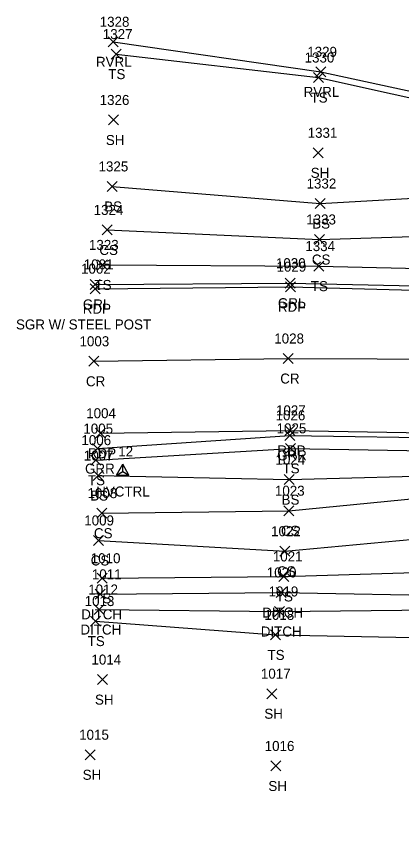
# Model space of a CAD drawing. Extents: x 1514253 to 1516033, y 782541 to 785002.
# Drawn here: x 1515182.9 to 1515259.8, y 782601.1 to 782767.3 of the extents above; entities that cross this region are included whole.
import ezdxf

# ---------------------------------------------------------------- set-up
doc = ezdxf.new("R2010")
doc.units = 0
for name, color, linetype in [('C_A', 7, 'Continuous'), ('C_I', 7, 'Continuous'), ('CPSM', 7, 'Continuous'), ('D_A', 7, 'Continuous'), ('D_I', 7, 'Continuous'), ('D_TIC', 7, 'Continuous'), ('DD', 7, 'Continuous'), ('L_A', 7, 'Continuous'), ('L_I', 7, 'Continuous'), ('L_TIC', 7, 'Continuous'), ('LAWE', 7, 'Continuous'), ('LELB', 7, 'Continuous'), ('P_A', 7, 'Continuous'), ('P_I', 7, 'Continuous'), ('P_TIC', 7, 'Continuous'), ('PET', 7, 'Continuous'), ('PRC', 7, 'Continuous'), ('R_A', 7, 'Continuous'), ('R_C', 7, 'Continuous'), ('R_I', 7, 'Continuous'), ('R_TIC', 7, 'Continuous'), ('RGR', 7, 'Continuous')]:
    doc.layers.add(name, color=color, linetype=linetype)

msp = doc.modelspace()

# ---------------------------------------------------------------- linework, layer by layer
at = {"layer": 'CPSM'}
for p, q in [((1515202.84, 782675.7), (1515204.09, 782677.87)), ((1515205.34, 782675.7), (1515204.09, 782677.87)), ((1515204.09, 782676.42), (1515204.09, 782677.87)), ((1515202.84, 782675.7), (1515204.09, 782676.42)), ((1515204.09, 782676.42), (1515204.09, 782676.42)), ((1515204.09, 782676.42), (1515205.34, 782675.7)), ((1515202.84, 782675.7), (1515205.34, 782675.7))]:
    msp.add_line(p, q, dxfattribs=at)
at = {"layer": 'D_TIC'}
for points in [[(1515198.55, 782650.88), (1515200.55, 782652.88)], [(1515200.55, 782650.88), (1515198.55, 782652.88)], [(1515234.76, 782651.24), (1515236.76, 782653.24)], [(1515236.76, 782651.24), (1515234.76, 782653.24)], [(1515198.39, 782647.84), (1515200.39, 782649.84)], [(1515200.39, 782647.84), (1515198.39, 782649.84)], [(1515234.48, 782647.45), (1515236.48, 782649.45)], [(1515236.48, 782647.45), (1515234.48, 782649.45)]]:
    msp.add_lwpolyline(points, dxfattribs=at)
at = {"layer": 'DD'}
for points in [[(1515199.55, 782651.88), (1515235.76, 782652.24), (1515272.28, 782651.56), (1515284.51, 782654.56), (1515294.12, 782653.93), (1515301.84, 782655.71), (1515302.59, 782655.7)], [(1515199.39, 782648.84), (1515235.48, 782648.45), (1515272.16, 782648.84), (1515285.61, 782648.49), (1515294.46, 782648.38), (1515312.17, 782640.18), (1515323.37, 782638.78), (1515329.31, 782640.31), (1515333.45, 782637.85), (1515333.04, 782633.95), (1515334.72, 782622.81), (1515328.39, 782601.12)]]:
    msp.add_lwpolyline(points, dxfattribs=at)
at = {"layer": 'L_TIC'}
for points in [[(1515201.17, 782761.27), (1515203.17, 782763.27)], [(1515203.17, 782761.27), (1515201.17, 782763.27)], [(1515201.79, 782758.81), (1515203.79, 782760.81)], [(1515203.79, 782758.81), (1515201.79, 782760.81)], [(1515242.26, 782754.13), (1515244.26, 782756.13)], [(1515244.26, 782754.13), (1515242.26, 782756.13)], [(1515242.71, 782755.27), (1515244.71, 782757.27)], [(1515244.71, 782755.27), (1515242.71, 782757.27)], [(1515201.22, 782745.65), (1515203.22, 782747.65)], [(1515203.22, 782745.65), (1515201.22, 782747.65)], [(1515242.22, 782739.09), (1515244.22, 782741.09)], [(1515244.22, 782739.09), (1515242.22, 782741.09)], [(1515200.95, 782732.37), (1515202.95, 782734.37)], [(1515202.95, 782732.37), (1515200.95, 782734.37)], [(1515242.57, 782728.95), (1515244.57, 782730.95)], [(1515244.57, 782728.95), (1515242.57, 782730.95)], [(1515199.97, 782723.68), (1515201.97, 782725.68)], [(1515201.97, 782723.68), (1515199.97, 782725.68)], [(1515242.49, 782721.77), (1515244.49, 782723.77)], [(1515244.49, 782721.77), (1515242.49, 782723.77)], [(1515199.03, 782716.69), (1515201.03, 782718.69)], [(1515201.03, 782716.69), (1515199.03, 782718.69)], [(1515242.31, 782716.45), (1515244.31, 782718.45)], [(1515244.31, 782716.45), (1515242.31, 782718.45)], [(1515236.65, 782680.04), (1515238.65, 782682.04)], [(1515238.65, 782680.04), (1515236.65, 782682.04)], [(1515197.72, 782677.68), (1515199.72, 782679.68)], [(1515199.72, 782677.68), (1515197.72, 782679.68)], [(1515198.15, 782674.61), (1515200.15, 782676.61)], [(1515200.15, 782674.61), (1515198.15, 782676.61)], [(1515236.42, 782673.79), (1515238.42, 782675.79)], [(1515238.42, 782673.79), (1515236.42, 782675.79)], [(1515236.31, 782667.58), (1515238.31, 782669.58)], [(1515238.31, 782667.58), (1515236.31, 782669.58)], [(1515198.89, 782667.09), (1515200.89, 782669.09)], [(1515200.89, 782667.09), (1515198.89, 782669.09)], [(1515198.25, 782661.64), (1515200.25, 782663.64)], [(1515200.25, 782661.64), (1515198.25, 782663.64)], [(1515235.54, 782659.48), (1515237.54, 782661.48)], [(1515237.54, 782659.48), (1515235.54, 782661.48)], [(1515198.98, 782654.09), (1515200.98, 782656.09)], [(1515200.98, 782654.09), (1515198.98, 782656.09)], [(1515235.32, 782654.45), (1515237.32, 782656.45)], [(1515237.32, 782654.45), (1515235.32, 782656.45)], [(1515197.67, 782645.53), (1515199.67, 782647.53)], [(1515199.67, 782645.53), (1515197.67, 782647.53)], [(1515233.65, 782642.77), (1515235.65, 782644.77)], [(1515235.65, 782642.77), (1515233.65, 782644.77)], [(1515199.04, 782633.84), (1515201.04, 782635.84)], [(1515201.04, 782633.84), (1515199.04, 782635.84)], [(1515232.94, 782631.02), (1515234.94, 782633.02)], [(1515234.94, 782631.02), (1515232.94, 782633.02)], [(1515196.58, 782618.82), (1515198.58, 782620.82)], [(1515198.58, 782618.82), (1515196.58, 782620.82)], [(1515233.75, 782616.58), (1515235.75, 782618.58)], [(1515235.75, 782616.58), (1515233.75, 782618.58)]]:
    msp.add_lwpolyline(points, dxfattribs=at)
at = {"layer": 'LAWE'}
msp.add_lwpolyline([(1515202.17, 782762.27), (1515243.71, 782756.27), (1515286.28, 782747.11), (1515297.44, 782750.04), (1515300.76, 782752.52), (1515315.46, 782751.02), (1515328.64, 782746.75), (1515343.2, 782744.52), (1515396.17, 782730.21), (1515410.48, 782726.67), (1515425.65, 782730.86), (1515462.57, 782730.18)], dxfattribs=at)
at = {"layer": 'LELB'}
for points in [[(1515202.79, 782759.81), (1515243.26, 782755.13), (1515286.87, 782745.48), (1515294.36, 782746.28), (1515301.46, 782734.49)], [(1515201.95, 782733.37), (1515243.57, 782729.95), (1515286.67, 782732.44), (1515301.66, 782731.52), (1515315.52, 782732.45), (1515331.94, 782733.39), (1515354.73, 782729.4), (1515394.7, 782722.81), (1515412.77, 782722.27)], [(1515200.97, 782724.68), (1515243.49, 782722.77), (1515286.83, 782724.14), (1515305.14, 782723.88), (1515320.01, 782723.69), (1515332.82, 782725.68), (1515355.56, 782722.1), (1515394.29, 782712.68), (1515425.22, 782714.96), (1515459.54, 782709.6)], [(1515200.03, 782717.69), (1515243.31, 782717.45), (1515286.69, 782716.43), (1515307.76, 782717.31)], [(1515198.72, 782678.68), (1515237.65, 782681.04), (1515272.58, 782680.41), (1515290.32, 782679.16), (1515303.85, 782678.5), (1515308.9, 782677.48), (1515327.05, 782677.39), (1515347.39, 782677.23), (1515355.31, 782675.99), (1515384.86, 782670.27), (1515402.64, 782668.14), (1515426.9, 782664.76), (1515431.08, 782662.88), (1515448.44, 782660.3)], [(1515199.15, 782675.61), (1515237.42, 782674.79), (1515272.57, 782675.73), (1515289.46, 782673.87), (1515300.03, 782673.18), (1515309.4, 782672.94), (1515327.02, 782671.99), (1515352.18, 782674.37), (1515355.48, 782668.37), (1515355.53, 782661.9), (1515362.2, 782656.24), (1515384.65, 782653.27), (1515398.96, 782656.38), (1515406.88, 782653.85), (1515416.3, 782653.12), (1515424.34, 782655.88), (1515430.38, 782659.61), (1515449.3, 782656.53)], [(1515199.98, 782655.09), (1515236.32, 782655.45), (1515273.42, 782656.6), (1515286.93, 782662.61), (1515299.54, 782665), (1515304.67, 782664.1), (1515305.27, 782661.39), (1515319.28, 782664.02), (1515324.87, 782660.75), (1515330.53, 782661.03), (1515335.53, 782663.34), (1515351.63, 782666.23), (1515352.18, 782674.37)], [(1515199.89, 782668.09), (1515237.31, 782668.58), (1515273.4, 782672.06), (1515287.73, 782668.03), (1515299.26, 782668.76), (1515308.35, 782666.42), (1515328.22, 782666.06), (1515330.53, 782661.03), (1515333.75, 782659.05), (1515343.88, 782659.19), (1515351.41, 782658.19), (1515355.48, 782668.37), (1515366.85, 782667.84), (1515384, 782666.14), (1515400.68, 782664.25), (1515424.65, 782661.72), (1515431.01, 782661.43), (1515448.86, 782658.44)], [(1515199.25, 782662.64), (1515236.54, 782660.48), (1515273.8, 782663.96), (1515286.93, 782662.61)], [(1515198.67, 782646.53), (1515234.65, 782643.77), (1515272.44, 782643.04), (1515272.72, 782635.52), (1515270.64, 782626.33), (1515264.31, 782620.96)]]:
    msp.add_lwpolyline(points, dxfattribs=at)
at = {"layer": 'P_TIC'}
for points in [[(1515236.64, 782712.34), (1515238.64, 782714.34)], [(1515238.64, 782712.34), (1515236.64, 782714.34)], [(1515197.6, 782711.94), (1515199.6, 782713.94)], [(1515199.6, 782711.94), (1515197.6, 782713.94)], [(1515197.29, 782697.44), (1515199.29, 782699.44)], [(1515199.29, 782697.44), (1515197.29, 782699.44)], [(1515236.18, 782697.99), (1515238.18, 782699.99)], [(1515238.18, 782697.99), (1515236.18, 782699.99)], [(1515198.63, 782683.06), (1515200.63, 782685.06)], [(1515200.63, 782683.06), (1515198.63, 782685.06)], [(1515236.52, 782683.63), (1515238.52, 782685.63)], [(1515238.52, 782683.63), (1515236.52, 782685.63)]]:
    msp.add_lwpolyline(points, dxfattribs=at)
at = {"layer": 'PET'}
for points in [[(1515198.6, 782712.94), (1515237.64, 782713.34), (1515272.2, 782712.4), (1515309.56, 782711.26), (1515351.19, 782708.16), (1515392.07, 782703.88), (1515423.17, 782699.74), (1515455.77, 782695.06)], [(1515199.63, 782684.06), (1515237.52, 782684.63), (1515272.46, 782684.04), (1515305.73, 782682.96), (1515349.74, 782679.79), (1515389.07, 782675.3), (1515418.68, 782671.11), (1515450.73, 782666.15)]]:
    msp.add_lwpolyline(points, dxfattribs=at)
at = {"layer": 'PRC'}
msp.add_lwpolyline([(1515198.29, 782698.44), (1515237.18, 782698.99), (1515272.83, 782698.88), (1515307.34, 782697.26), (1515350.13, 782694.48), (1515391.03, 782689.51), (1515420.87, 782685.75), (1515453.49, 782680.58)], dxfattribs=at)
at = {"layer": 'R_TIC'}
for points in [[(1515197.57, 782712.8), (1515199.57, 782714.8)], [(1515199.57, 782712.8), (1515197.57, 782714.8)], [(1515236.6, 782713.04), (1515238.6, 782715.04)], [(1515238.6, 782713.04), (1515236.6, 782715.04)], [(1515236.5, 782682.64), (1515238.5, 782684.64)], [(1515238.5, 782682.64), (1515236.5, 782684.64)], [(1515198.06, 782679.99), (1515200.06, 782681.99)], [(1515200.06, 782679.99), (1515198.06, 782681.99)]]:
    msp.add_lwpolyline(points, dxfattribs=at)
at = {"layer": 'RGR'}
for points in [[(1515198.57, 782713.8), (1515237.6, 782714.04), (1515271.88, 782713.33), (1515309.65, 782711.93), (1515351.2, 782708.69), (1515392.07, 782704.46), (1515423.15, 782700.51), (1515456.3, 782695.76)], [(1515199.06, 782680.99), (1515237.5, 782683.64), (1515272.43, 782683.08), (1515305.96, 782681.52), (1515350.17, 782679.41), (1515389, 782674.46), (1515418.69, 782670.32), (1515449.27, 782662.37)]]:
    msp.add_lwpolyline(points, dxfattribs=at)

# ---------------------------------------------------------------- texts
at = {"layer": 'C_A'}
msp.add_text('HVCTRL', height=2, dxfattribs=at).set_placement((1515198.78, 782671.42))
at = {"layer": 'C_I'}
msp.add_text('12', height=2, dxfattribs=at).set_placement((1515203.19, 782679.42))
at = {"layer": 'D_A'}
for p in [(1515195.78, 782646.88), (1515232, 782647.24), (1515195.63, 782643.84), (1515231.72, 782643.45)]:
    msp.add_text('DITCH', height=2, dxfattribs=at).set_placement(p)
at = {"layer": 'D_I'}
for s, p in [('1011', (1515197.91, 782654.88)), ('1020', (1515232.91, 782655.24)), ('1012', (1515197.19, 782651.84)), ('1019', (1515233.27, 782651.45))]:
    msp.add_text(s, height=2, dxfattribs=at).set_placement(p)
at = {"layer": 'L_A'}
for s, p in [('RVRL', (1515198.74, 782757.27)), ('TS', (1515201.2, 782754.81)), ('RVRL', (1515240.28, 782751.27)), ('TS', (1515241.67, 782750.13)), ('SH', (1515200.71, 782741.65)), ('SH', (1515241.7, 782735.09)), ('BS', (1515200.39, 782728.37)), ('BS', (1515242.01, 782724.95)), ('CS', (1515199.41, 782719.68)), ('CS', (1515241.93, 782717.77)), ('TS', (1515198.44, 782712.69)), ('TS', (1515241.72, 782712.45)), ('TS', (1515236.06, 782676.04)), ('TS', (1515197.13, 782673.68)), ('BS', (1515197.59, 782670.61)), ('BS', (1515235.87, 782669.79)), ('CS', (1515198.33, 782663.09)), ('CS', (1515235.75, 782663.58)), ('CS', (1515197.69, 782657.64)), ('CS', (1515234.98, 782655.48)), ('TS', (1515198.39, 782650.09)), ('TS', (1515234.73, 782650.45)), ('TS', (1515197.08, 782641.53)), ('TS', (1515233.06, 782638.77)), ('SH', (1515198.53, 782629.84)), ('SH', (1515232.42, 782627.02)), ('SH', (1515196.07, 782614.82)), ('SH', (1515233.23, 782612.58))]:
    msp.add_text(s, height=2, dxfattribs=at).set_placement(p)
at = {"layer": 'L_I'}
for s, p in [('1328', (1515199.48, 782765.27)), ('1327', (1515200.1, 782762.81)), ('1329', (1515241.01, 782759.27)), ('1330', (1515240.48, 782758.13)), ('1326', (1515199.47, 782749.65)), ('1331', (1515241.09, 782743.09)), ('1325', (1515199.25, 782736.37)), ('1332', (1515240.87, 782732.95)), ('1324', (1515198.27, 782727.68)), ('1333', (1515240.8, 782725.77)), ('1323', (1515197.33, 782720.69)), ('1334', (1515240.62, 782720.45)), ('1025', (1515234.88, 782684.04)), ('1006', (1515195.82, 782681.68)), ('1007', (1515196.3, 782678.61)), ('1024', (1515234.65, 782677.79)), ('1008', (1515197.04, 782671.09)), ('1023', (1515234.54, 782671.58)), ('1009', (1515196.39, 782665.64)), ('1022', (1515233.77, 782663.48)), ('1010', (1515197.69, 782658.09)), ('1021', (1515234.12, 782658.45)), ('1013', (1515196.47, 782649.53)), ('1018', (1515232.45, 782646.77)), ('1014', (1515197.83, 782637.84)), ('1017', (1515231.73, 782635.02)), ('1015', (1515195.37, 782622.82)), ('1016', (1515232.49, 782620.58))]:
    msp.add_text(s, height=2, dxfattribs=at).set_placement(p)
at = {"layer": 'P_A'}
for s, p in [('RDP', (1515196.09, 782707.94)), ('RDP', (1515235.13, 782708.34)), ('CR', (1515235.61, 782693.99)), ('CR', (1515196.73, 782693.44)), ('RDP', (1515197.12, 782679.06)), ('RDP', (1515235.01, 782679.63))]:
    msp.add_text(s, height=2, dxfattribs=at).set_placement(p)
at = {"layer": 'P_I'}
for s, p in [('1002', (1515195.75, 782715.94)), ('1029', (1515234.86, 782716.34)), ('1003', (1515195.44, 782701.44)), ('1028', (1515234.41, 782701.99)), ('1027', (1515234.75, 782687.63)), ('1004', (1515196.78, 782687.06))]:
    msp.add_text(s, height=2, dxfattribs=at).set_placement(p)
at = {"layer": 'R_A'}
for s, p in [('GRL', (1515196.11, 782708.8)), ('GRL', (1515235.14, 782709.04)), ('GRR', (1515234.98, 782678.64)), ('GRR', (1515196.55, 782675.99))]:
    msp.add_text(s, height=2, dxfattribs=at).set_placement(p)
at = {"layer": 'R_C'}
msp.add_text('SGR W/ STEEL POST', height=2, dxfattribs=at).set_placement((1515182.73, 782704.8))
at = {"layer": 'R_I'}
for s, p in [('1030', (1515234.74, 782717.04)), ('1001', (1515196.29, 782716.8)), ('1026', (1515234.67, 782686.64)), ('1005', (1515196.21, 782683.99))]:
    msp.add_text(s, height=2, dxfattribs=at).set_placement(p)

doc.saveas('drawing.dxf')
